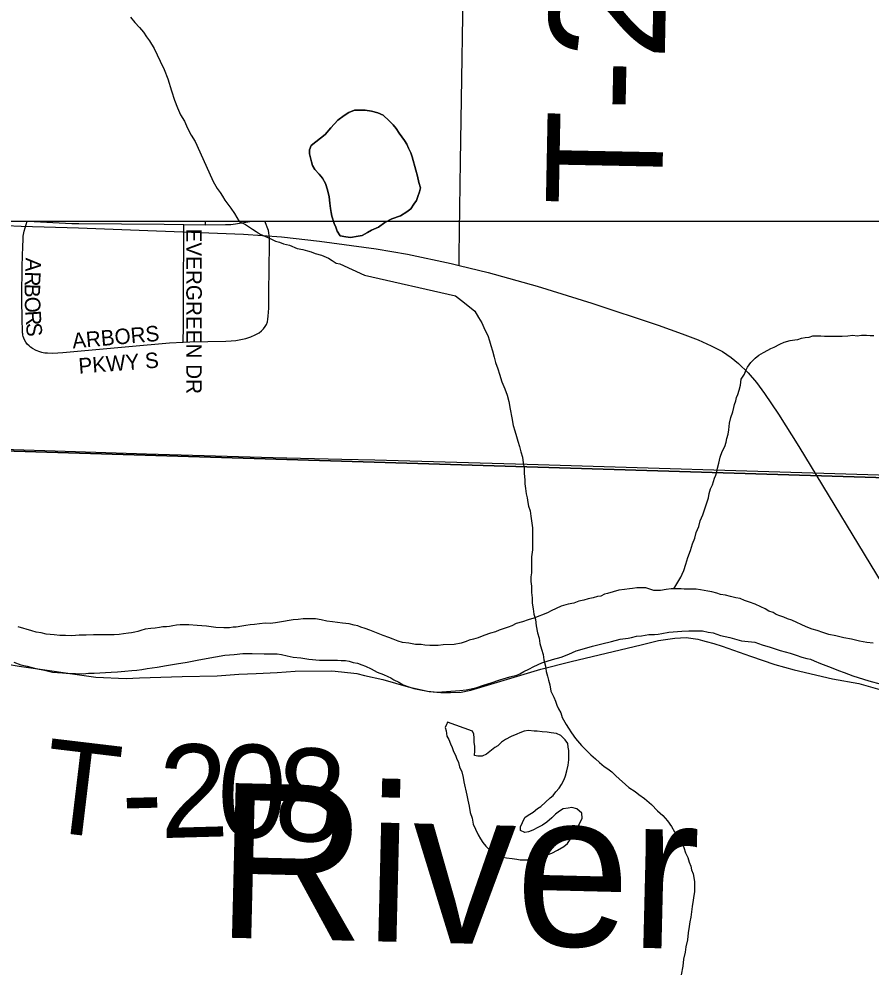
# Model space of a CAD drawing. Extents: x 0 to 68, y 0 to 52.9.
# Drawn here: x 47.168 to 47.718, y 38.053 to 38.666 of the extents above; entities that cross this region are included whole.
import ezdxf

# ---------------------------------------------------------------- set-up
doc = ezdxf.new("R2010")
doc.units = 0
for name, color, linetype in [('Default', 7, 'Continuous'), ('GM_X_Minor_Lake', 7, 'Continuous'), ('GM_X_Minor_River', 7, 'Continuous'), ('GM_X_State_Route', 7, 'Continuous'), ('GM_X_Township_Road', 7, 'Continuous'), ('GM_X_Township_Road_Text', 7, 'Continuous')]:
    doc.layers.add(name, color=color, linetype=linetype)

msp = doc.modelspace()

# ---------------------------------------------------------------- linework, layer by layer
at = {"layer": 'Default'}
msp.add_line((42.25806, 38.53508), (49.65006, 38.53508), dxfattribs=at)
for points in [[(48.1746, 38.53508), (48.17291, 38.35564), (47.10782, 38.38814), (47.10988, 38.53508)], [(47.17613, 38.45297), (47.17507, 38.45367), (47.17419, 38.45443), (47.17299, 38.45563), (47.1721, 38.4569), (47.17132, 38.45831), (47.17075, 38.45953), (47.1704, 38.46053), (47.17018, 38.46142), (47.17008, 38.4623), (47.17002, 38.463), (47.16993, 38.46404), (47.16991, 38.46579), (47.16975, 38.47014), (47.16946, 38.48614), (47.16973, 38.50602), (47.17025, 38.51888), (47.17028, 38.52313), (47.17046, 38.52544), (47.17111, 38.52868), (47.17303, 38.53508)], [(47.17327, 38.53508), (47.20189, 38.53355), (47.20636, 38.53352)], [(47.20636, 38.53352), (47.26148, 38.53314), (47.27416, 38.53294)], [(47.27374, 38.45694), (47.2739, 38.46699), (47.27393, 38.49056), (47.27418, 38.52716), (47.27416, 38.53294)], [(47.27416, 38.53294), (47.28827, 38.53272)], [(47.28827, 38.53272), (47.28829, 38.53508)], [(47.28827, 38.53272), (47.30109, 38.53287), (47.30453, 38.53298), (47.3076, 38.53335), (47.31811, 38.53508)], [(47.32574, 38.46551), (47.32682, 38.46699), (47.32759, 38.46837), (47.32825, 38.47014), (47.3286, 38.47178), (47.32878, 38.47364), (47.32905, 38.47882), (47.32917, 38.48892), (47.32961, 38.52014), (47.32955, 38.52407), (47.32943, 38.52593), (47.32912, 38.52759), (47.32887, 38.52907), (47.32666, 38.53508)], [(47.27374, 38.45694), (47.27816, 38.45718), (47.30127, 38.45753), (47.30471, 38.45773), (47.30785, 38.45806), (47.31108, 38.45858), (47.3143, 38.45932), (47.31742, 38.46034), (47.32023, 38.46163), (47.32284, 38.46303), (47.32436, 38.46424), (47.32574, 38.46551)], [(47.17613, 38.45297), (47.17863, 38.45175), (47.18085, 38.45083), (47.18214, 38.45045), (47.18427, 38.45008), (47.18614, 38.44997), (47.18943, 38.44989), (47.19601, 38.45016), (47.2387, 38.45417), (47.26498, 38.45646), (47.27374, 38.45694)], [(47.71972, 38.26238), (47.7157, 38.26283), (47.71087, 38.2637), (47.70565, 38.26497), (47.70083, 38.26584), (47.69561, 38.26712), (47.69119, 38.26798), (47.68718, 38.26923), (47.68357, 38.27049), (47.68035, 38.27133), (47.67635, 38.27299), (47.66713, 38.27713), (47.66432, 38.27797), (47.66192, 38.27921), (47.65952, 38.28005), (47.65711, 38.28088), (47.65511, 38.28211), (47.6523, 38.28295), (47.6499, 38.28459), (47.6471, 38.28583), (47.6435, 38.28749), (47.63988, 38.28874), (47.63668, 38.28999), (47.63387, 38.29123), (47.63106, 38.29167), (47.62744, 38.29252), (47.62423, 38.29337), (47.62101, 38.29381), (47.61861, 38.29464), (47.6154, 38.29549), (47.61298, 38.29592), (47.61057, 38.29636), (47.60816, 38.29679), (47.60535, 38.29723), (47.60253, 38.29727), (47.59971, 38.2973), (47.59769, 38.29733), (47.59568, 38.29736), (47.59286, 38.29739), (47.58924, 38.29744), (47.58601, 38.29708), (47.58237, 38.29633), (47.57794, 38.29639), (47.57273, 38.29806), (47.56991, 38.2981), (47.56709, 38.29813), (47.56426, 38.29777), (47.56224, 38.2974), (47.55901, 38.29704), (47.55539, 38.29668), (47.55174, 38.29552), (47.54811, 38.29437), (47.54608, 38.29399), (47.54365, 38.29282)], [(47.54365, 38.29282), (47.54164, 38.29244), (47.5388, 38.29167), (47.53557, 38.29092), (47.53274, 38.29015), (47.52951, 38.28939), (47.52627, 38.28822), (47.52264, 38.28747), (47.51819, 38.28632), (47.51495, 38.28476), (47.51171, 38.28319), (47.50927, 38.28202), (47.50037, 38.27852), (47.49673, 38.27736), (47.49309, 38.2762), (47.48904, 38.27505), (47.4862, 38.27348), (47.48378, 38.27271), (47.48054, 38.27155), (47.47811, 38.27078), (47.47568, 38.2696), (47.47245, 38.26884), (47.468, 38.26729), (47.46435, 38.26573), (47.46152, 38.26497), (47.45869, 38.2642), (47.45667, 38.26342), (47.45343, 38.26226), (47.44899, 38.26151), (47.44173, 38.26121), (47.43851, 38.26085), (47.43649, 38.26088), (47.43327, 38.26092), (47.43005, 38.26096), (47.42764, 38.26139), (47.42401, 38.26144), (47.41959, 38.2623), (47.41557, 38.26276), (47.41276, 38.2636), (47.40955, 38.26485), (47.40675, 38.26609), (47.40314, 38.26734), (47.39873, 38.26901), (47.39432, 38.27067), (47.39151, 38.27191), (47.3887, 38.27275), (47.3867, 38.27358), (47.38429, 38.27402), (47.38108, 38.27486), (47.37665, 38.27532), (47.37343, 38.27577), (47.37022, 38.27621), (47.3666, 38.27666), (47.36298, 38.27751), (47.35936, 38.27796), (47.35533, 38.27801), (47.35131, 38.27807), (47.34808, 38.27771), (47.34485, 38.27735), (47.33597, 38.27586), (47.33355, 38.27549), (47.32992, 38.27513), (47.32669, 38.27518), (47.32307, 38.27482), (47.31984, 38.27446), (47.31701, 38.2741), (47.31419, 38.27373), (47.31177, 38.27336), (47.30813, 38.27261), (47.30612, 38.27263), (47.30369, 38.27226), (47.30007, 38.27231), (47.29483, 38.27238), (47.2888, 38.27326), (47.28277, 38.27374), (47.27753, 38.27421), (47.2719, 38.27429), (47.26947, 38.27392), (47.26705, 38.27355), (47.26503, 38.27317), (47.26301, 38.2728), (47.2606, 38.27283), (47.25858, 38.27245), (47.25575, 38.27209), (47.25293, 38.27172), (47.2493, 38.27137), (47.24647, 38.2706), (47.24445, 38.26983), (47.24243, 38.26945), (47.24041, 38.26907), (47.23839, 38.2687), (47.23516, 38.26834), (47.23234, 38.26798), (47.22911, 38.26762), (47.22468, 38.26768), (47.22025, 38.26773), (47.21582, 38.26779), (47.21098, 38.26745), (47.20655, 38.26751), (47.20171, 38.26717), (47.19768, 38.26723)], [(47.19768, 38.26723), (47.19406, 38.26727), (47.19044, 38.26772), (47.18521, 38.26819), (47.18199, 38.26904), (47.17878, 38.26948), (47.17597, 38.27032), (47.16714, 38.27285)], [(47.43813, 38.23072), (47.45264, 38.23174), (47.45667, 38.23208), (47.45991, 38.23284), (47.46354, 38.2336), (47.46799, 38.23515), (47.47285, 38.23669), (47.47851, 38.23863), (47.48498, 38.24055), (47.48943, 38.2417), (47.49145, 38.24247), (47.49389, 38.24405), (47.49713, 38.24561), (47.50037, 38.24718), (47.50564, 38.24952), (47.51252, 38.25184), (47.51818, 38.25338), (47.52304, 38.25532), (47.52789, 38.25727), (47.53315, 38.2588), (47.53841, 38.26034), (47.54447, 38.26187), (47.55053, 38.2634), (47.55619, 38.26493), (47.56144, 38.26566), (47.56346, 38.26604), (47.56669, 38.2668), (47.56992, 38.26716), (47.57234, 38.26753), (47.57476, 38.2679), (47.57839, 38.26785), (47.58081, 38.26822), (47.58323, 38.26859), (47.58767, 38.26934), (47.59614, 38.27003), (47.60058, 38.27037), (47.60299, 38.27034), (47.60662, 38.27029), (47.60944, 38.27026), (47.61305, 38.2694), (47.61627, 38.26896), (47.61867, 38.26812), (47.62108, 38.26729), (47.62711, 38.26601), (47.63474, 38.2639), (47.64319, 38.26298), (47.648, 38.26131), (47.65321, 38.25964), (47.65963, 38.25754), (47.66606, 38.25585), (47.67007, 38.25459), (47.67368, 38.25334), (47.67689, 38.25249), (47.6793, 38.25206), (47.68171, 38.25082), (47.68571, 38.24916), (47.69253, 38.24666), (47.69734, 38.24459), (47.70095, 38.24334), (47.70656, 38.24126), (47.71699, 38.2379), (47.72502, 38.23579)], [(47.16443, 38.24998), (47.16884, 38.24832), (47.17286, 38.24746), (47.17607, 38.24662), (47.17969, 38.24577), (47.18411, 38.2449), (47.18933, 38.24363), (47.19577, 38.24314), (47.2006, 38.24268), (47.20422, 38.24263), (47.20905, 38.24257), (47.21268, 38.24292), (47.21631, 38.24287), (47.22719, 38.24353), (47.23123, 38.24388), (47.23607, 38.24422), (47.2405, 38.24456), (47.24373, 38.24492), (47.24696, 38.24528), (47.25059, 38.24604), (47.25704, 38.24676), (47.2631, 38.24788), (47.26956, 38.249), (47.27643, 38.25012), (47.28288, 38.25124), (47.28854, 38.25237), (47.2946, 38.2535), (47.30065, 38.25462), (47.3067, 38.25495), (47.31235, 38.25568), (47.31839, 38.2556), (47.32604, 38.2555), (47.33088, 38.25543), (47.3345, 38.25538), (47.33732, 38.25495), (47.34093, 38.25409), (47.34495, 38.25324), (47.34978, 38.25277), (47.355, 38.2519), (47.36185, 38.25141), (47.36869, 38.25132), (47.37353, 38.25126), (47.37594, 38.25122), (47.37876, 38.25119), (47.38117, 38.25075), (47.38358, 38.24992), (47.38639, 38.24948), (47.3892, 38.24824), (47.39161, 38.2474), (47.39521, 38.24575), (47.39921, 38.24369), (47.40322, 38.24203), (47.40602, 38.24078), (47.40803, 38.23996), (47.41003, 38.23872), (47.41323, 38.23707), (47.41603, 38.23543), (47.41964, 38.23418), (47.42285, 38.23293), (47.42727, 38.23207), (47.43169, 38.23121), (47.43813, 38.23072)]]:
    msp.add_lwpolyline(points, dxfattribs=at)
msp.add_lwpolyline([(47.10782, 38.38814), (48.17291, 38.35564), (48.15695, 37.30357), (47.09744, 37.33201)], close=True, dxfattribs=at)
at = {"layer": 'GM_X_Minor_Lake'}
for points in [[(47.35645, 38.58412), (47.3656, 38.59103), (47.36918, 38.5955), (47.37378, 38.60046), (47.37784, 38.60342), (47.38089, 38.60539), (47.38443, 38.60685), (47.38795, 38.60681), (47.39148, 38.60676), (47.3955, 38.60621), (47.39951, 38.60515), (47.40302, 38.6036), (47.407, 38.60003), (47.40949, 38.59749), (47.41147, 38.59495), (47.41345, 38.59191), (47.41691, 38.58734), (47.41839, 38.58481), (47.41937, 38.58229), (47.42084, 38.57926), (47.42181, 38.57673), (47.42422, 38.56816), (47.42518, 38.56413), (47.42614, 38.5601), (47.4271, 38.55657), (47.42656, 38.55407), (47.42552, 38.55107), (47.42448, 38.54857), (47.42294, 38.54608), (47.42089, 38.54309), (47.41835, 38.54112), (47.41428, 38.53866), (47.40872, 38.53672), (47.40416, 38.53427), (47.40009, 38.53131), (47.39554, 38.52936), (47.393, 38.52789), (47.38945, 38.52593), (47.38693, 38.52546), (47.38188, 38.52452), (47.37887, 38.52506), (47.37535, 38.52561), (47.37337, 38.52865), (47.3724, 38.53117), (47.37142, 38.5337), (47.36997, 38.53824), (47.3695, 38.54075), (47.36903, 38.54327), (47.36857, 38.54679), (47.36811, 38.55082), (47.36716, 38.55535), (47.3657, 38.55939), (47.36373, 38.56293), (47.36175, 38.56547), (47.35877, 38.56852), (47.35729, 38.57105), (47.35682, 38.57357), (47.35537, 38.57861), (47.3554, 38.58112), (47.35645, 38.58412)], [(47.42089, 38.54309), (47.42294, 38.54608), (47.42448, 38.54857), (47.42552, 38.55107), (47.42656, 38.55407), (47.4271, 38.55657), (47.42614, 38.5601), (47.42518, 38.56413), (47.42422, 38.56816), (47.42181, 38.57673), (47.42084, 38.57926), (47.41937, 38.58229), (47.41839, 38.58481), (47.41691, 38.58734), (47.41345, 38.59191), (47.41147, 38.59495), (47.40949, 38.59749), (47.407, 38.60003), (47.40302, 38.6036), (47.39951, 38.60515), (47.3955, 38.60621), (47.39148, 38.60676), (47.38795, 38.60681), (47.38443, 38.60685), (47.38089, 38.60539), (47.37784, 38.60342), (47.37378, 38.60046), (47.36918, 38.5955), (47.3656, 38.59103), (47.35645, 38.58412)], [(47.35645, 38.58412), (47.3554, 38.58112), (47.35537, 38.57861), (47.35682, 38.57357), (47.35729, 38.57105), (47.35877, 38.56852), (47.36175, 38.56547), (47.36373, 38.56293), (47.3657, 38.55939), (47.36716, 38.55535), (47.36811, 38.55082), (47.36857, 38.54679), (47.36903, 38.54327), (47.3695, 38.54075), (47.36997, 38.53824), (47.37142, 38.5337), (47.3724, 38.53117), (47.37337, 38.52865), (47.37535, 38.52561), (47.37887, 38.52506), (47.38188, 38.52452), (47.38693, 38.52546), (47.38945, 38.52593), (47.393, 38.52789), (47.39554, 38.52936), (47.40009, 38.53131), (47.40416, 38.53427), (47.40872, 38.53672), (47.41428, 38.53866), (47.41835, 38.54112), (47.42089, 38.54309)], [(47.44473, 38.21135), (47.44432, 38.21055), (47.4439, 38.20975), (47.44307, 38.20775), (47.44385, 38.20573), (47.44421, 38.20211), (47.44539, 38.20009), (47.44656, 38.19726), (47.44774, 38.19483), (47.44852, 38.19241), (47.4497, 38.18999), (47.45048, 38.18797), (47.45165, 38.18514), (47.45242, 38.18232), (47.45399, 38.17908), (47.45475, 38.17546), (47.45512, 38.17264)], [(47.45512, 38.17264), (47.45702, 38.16418), (47.45779, 38.16095), (47.45854, 38.15692), (47.4593, 38.1529), (47.46046, 38.14926), (47.46122, 38.14523), (47.46279, 38.142), (47.46435, 38.13836), (47.46593, 38.13593), (47.46751, 38.1335), (47.4695, 38.13106), (47.47149, 38.12903), (47.47348, 38.12739), (47.47707, 38.12494), (47.48029, 38.12409), (47.4827, 38.12366), (47.48632, 38.12321), (47.48954, 38.12277), (47.49154, 38.12234), (47.49356, 38.12231), (47.49678, 38.12227), (47.4988, 38.12264), (47.50082, 38.12302), (47.50325, 38.12379), (47.50526, 38.12416), (47.50729, 38.12494), (47.51214, 38.12648), (47.51579, 38.12845), (47.51985, 38.1308), (47.52229, 38.13278), (47.52353, 38.13477), (47.52476, 38.13677), (47.52641, 38.13956), (47.52888, 38.14354), (47.53053, 38.14674), (47.53177, 38.14913), (47.5314, 38.15235), (47.52822, 38.1552), (47.525, 38.15605), (47.52258, 38.15568), (47.51936, 38.15532), (47.51692, 38.15374), (47.51448, 38.15177), (47.51203, 38.14939), (47.50877, 38.14662), (47.50593, 38.14465), (47.50309, 38.14308), (47.49984, 38.14151), (47.49701, 38.14035), (47.49459, 38.13997), (47.49178, 38.14122), (47.49181, 38.14363), (47.49306, 38.14643), (47.49471, 38.14962), (47.49674, 38.1512), (47.49999, 38.15316), (47.50284, 38.15554), (47.50487, 38.15672), (47.51098, 38.16226), (47.51302, 38.16384), (47.51466, 38.16623), (47.5167, 38.16862), (47.51834, 38.171), (47.52, 38.1742), (47.52083, 38.1766), (47.52168, 38.1798), (47.52253, 38.1834), (47.52298, 38.18701), (47.52302, 38.19023), (47.52305, 38.19304), (47.52268, 38.19506), (47.5223, 38.19747), (47.52072, 38.1999), (47.51794, 38.20275), (47.51514, 38.20399), (47.51152, 38.20444), (47.5091, 38.20488), (47.50588, 38.20492), (47.50266, 38.20536), (47.50065, 38.20539), (47.49703, 38.20584), (47.49421, 38.20547), (47.49137, 38.20431), (47.48935, 38.20353), (47.4857, 38.20197), (47.48205, 38.20001), (47.47961, 38.19843), (47.47717, 38.19605), (47.47514, 38.19487), (47.46985, 38.19052), (47.46701, 38.18936), (47.46419, 38.18939), (47.46218, 38.18982), (47.46222, 38.19263), (47.46225, 38.19545), (47.46189, 38.19826), (47.46192, 38.20108), (47.46155, 38.20349), (47.46077, 38.20551), (47.44473, 38.21135)]]:
    msp.add_lwpolyline(points, dxfattribs=at)
at = {"layer": 'GM_X_Minor_River'}
for points in [[(47.23966, 38.66701), (47.24264, 38.66346), (47.24562, 38.66041), (47.2481, 38.65736), (47.25008, 38.65432), (47.25206, 38.65178), (47.25502, 38.64672), (47.25698, 38.64268), (47.25894, 38.63864), (47.26139, 38.63308), (47.26383, 38.62702), (47.26626, 38.61945), (47.26819, 38.6134), (47.27014, 38.60835), (47.2721, 38.60381), (47.27457, 38.59976), (47.27652, 38.59521), (47.27898, 38.59066), (47.28145, 38.58661), (47.29027, 38.56691), (47.29321, 38.56084), (47.29567, 38.55629), (47.29765, 38.55375), (47.29913, 38.55122), (47.30061, 38.54869), (47.3026, 38.54615), (47.30458, 38.54361), (47.30705, 38.54007), (47.31001, 38.535), (47.31401, 38.53294), (47.3185, 38.52987), (47.321, 38.52833), (47.3235, 38.52679), (47.327, 38.52524), (47.33051, 38.52368), (47.33351, 38.52214), (47.33602, 38.5216), (47.33853, 38.52057), (47.34254, 38.51951), (47.34755, 38.51743), (47.35107, 38.51689), (47.35408, 38.51584), (47.35659, 38.51531), (47.35909, 38.51427), (47.36311, 38.51321), (47.36761, 38.51115), (47.37011, 38.50961), (47.37261, 38.50807), (47.37512, 38.50753), (47.39094, 38.50017)], [(47.39094, 38.50017), (47.44971, 38.48694), (47.45372, 38.48392), (47.45672, 38.4814), (47.46223, 38.47687), (47.46473, 38.47285), (47.46673, 38.46933), (47.46872, 38.46481), (47.47072, 38.46129), (47.47172, 38.45778), (47.47271, 38.45476), (47.47371, 38.45125), (47.4747, 38.44723), (47.4757, 38.44372), (47.4772, 38.4397), (47.47819, 38.43619), (47.47968, 38.43116), (47.48168, 38.42664), (47.48318, 38.42262), (47.48417, 38.41861), (47.48516, 38.41359), (47.48615, 38.40807), (47.48714, 38.40305), (47.48814, 38.39953), (47.48914, 38.39602), (47.49013, 38.393), (47.49113, 38.38949), (47.49212, 38.38597), (47.49312, 38.38246), (47.49361, 38.37895), (47.49411, 38.37543), (47.4941, 38.37192), (47.49459, 38.36791), (47.49458, 38.3654), (47.49508, 38.36239), (47.49557, 38.35887), (47.49607, 38.35637), (47.49656, 38.35335), (47.49706, 38.35084), (47.49806, 38.34783), (47.49855, 38.34432), (47.49904, 38.3398), (47.49954, 38.33679), (47.49952, 38.32826), (47.49951, 38.32575), (47.4995, 38.32274), (47.49899, 38.31823), (47.49898, 38.31472), (47.49897, 38.3102), (47.49897, 38.30769), (47.49846, 38.30519), (47.49845, 38.30218), (47.49895, 38.29917), (47.49894, 38.29515), (47.49943, 38.29164), (47.49942, 38.28813), (47.49992, 38.28461), (47.50041, 38.2811), (47.50141, 38.27759), (47.5019, 38.27357), (47.50289, 38.26905), (47.50389, 38.26554), (47.50438, 38.26203), (47.50538, 38.25851), (47.50637, 38.255), (47.50686, 38.25148), (47.50786, 38.24747), (47.50835, 38.24395), (47.50935, 38.24094), (47.50984, 38.23843), (47.51084, 38.23542), (47.51133, 38.2314), (47.51333, 38.22738), (47.51433, 38.22487), (47.51533, 38.22236), (47.51632, 38.21985), (47.51782, 38.21734), (47.51882, 38.21432), (47.52132, 38.2098), (47.52282, 38.20729), (47.52482, 38.20427), (47.52732, 38.20075), (47.53132, 38.19622), (47.53433, 38.1932), (47.53733, 38.19018), (47.54033, 38.18767), (47.54283, 38.18515), (47.54584, 38.18263), (47.54834, 38.18112), (47.55085, 38.1791), (47.55335, 38.17659), (47.56186, 38.16904), (47.56587, 38.16651), (47.56837, 38.1645), (47.57188, 38.16198), (47.57639, 38.15795), (47.58039, 38.15393), (47.5839, 38.15091), (47.5869, 38.14739), (47.5894, 38.14386), (47.5914, 38.14035)], [(47.59092, 38.29742), (47.59537, 38.30499), (47.5962, 38.30699), (47.59744, 38.30939), (47.5987, 38.31339), (47.59997, 38.31779), (47.60163, 38.32219), (47.6029, 38.32659), (47.60455, 38.33019), (47.60541, 38.33379), (47.60707, 38.33779), (47.60792, 38.34139), (47.60958, 38.34539), (47.61251, 38.35379), (47.61334, 38.35619), (47.61378, 38.359), (47.61463, 38.3622), (47.61587, 38.36459), (47.61713, 38.369), (47.61796, 38.371), (47.61879, 38.37299), (47.61923, 38.3754), (47.62007, 38.3786), (47.62093, 38.38261), (47.62218, 38.38621), (47.62384, 38.3894), (47.62468, 38.3922), (47.62511, 38.39461), (47.62595, 38.39741), (47.62639, 38.40022), (47.62685, 38.40463), (47.6277, 38.40823), (47.62895, 38.41183), (47.62979, 38.41464), (47.63022, 38.41664), (47.63106, 38.41904), (47.63149, 38.42104), (47.63232, 38.42304), (47.63316, 38.42584), (47.63401, 38.42904), (47.63446, 38.43306), (47.63651, 38.43624), (47.63735, 38.43864), (47.63858, 38.44064), (47.64064, 38.44382), (47.64349, 38.4466), (47.64594, 38.44857), (47.64878, 38.45014), (47.65162, 38.45171), (47.65365, 38.45289), (47.65567, 38.45367), (47.65932, 38.45563), (47.66216, 38.4568), (47.6662, 38.45795), (47.66902, 38.45832), (47.67104, 38.45869), (47.67347, 38.45946), (47.67589, 38.45983), (47.67831, 38.4602), (47.68074, 38.46097), (47.68316, 38.46094), (47.68598, 38.46091), (47.68839, 38.46087), (47.69081, 38.46084), (47.69282, 38.46082), (47.69645, 38.46077), (47.69967, 38.46073), (47.7033, 38.46108), (47.70653, 38.46144), (47.70934, 38.461), (47.71217, 38.46137), (47.71539, 38.46132), (47.71781, 38.46129), (47.72022, 38.46126)], [(47.5914, 38.14035), (47.5934, 38.13783), (47.5954, 38.13431), (47.5974, 38.13029), (47.59839, 38.12678), (47.59989, 38.12377), (47.60088, 38.12075), (47.60188, 38.11824), (47.60238, 38.11573), (47.60338, 38.11322), (47.60437, 38.1082), (47.60436, 38.10519), (47.60435, 38.10168), (47.60385, 38.09917), (47.60334, 38.09616), (47.60283, 38.09215), (47.60232, 38.08864), (47.60181, 38.08513), (47.6013, 38.08212), (47.60079, 38.07912), (47.60028, 38.0751), (47.59977, 38.07059), (47.59875, 38.06608), (47.59824, 38.06257), (47.59723, 38.05806), (47.59672, 38.05354), (47.5957, 38.04803)]]:
    msp.add_lwpolyline(points, dxfattribs=at)
at = {"layer": 'GM_X_State_Route'}
for points in [[(46.80943, 38.66708), (46.82386, 38.65937), (46.8826, 38.63006), (46.98861, 38.57593), (47.01807, 38.56147), (47.03299, 38.55475), (47.04821, 38.54875), (47.05983, 38.54493), (47.0756, 38.54067), (47.09163, 38.53749), (47.10374, 38.53567), (47.12035, 38.53414), (47.16917, 38.53186), (47.20611, 38.53072), (47.31276, 38.52664), (47.33737, 38.52491), (47.36189, 38.5222), (47.39852, 38.51713), (47.4188, 38.51373), (47.44696, 38.50778), (47.4521, 38.50651)], [(47.4521, 38.50651), (47.47091, 38.50189), (47.5026, 38.49314), (47.53791, 38.48219), (47.58079, 38.46787), (47.5963, 38.46225), (47.6066, 38.45833), (47.61496, 38.45457), (47.62228, 38.45081), (47.62792, 38.44705), (47.63273, 38.44308), (47.63901, 38.43702), (47.64424, 38.43075), (47.64947, 38.42365), (47.6586, 38.4104), (47.67171, 38.38946), (47.72913, 38.29467)], [(46.89942, 38.39698), (46.94005, 38.3952), (47.01248, 38.39244), (47.04831, 38.39119), (47.0711, 38.3904), (47.09079, 38.38961), (47.1101, 38.3893), (47.19098, 38.38658), (47.25002, 38.3847), (47.33202, 38.38237), (47.37632, 38.38135), (47.39764, 38.38085), (47.49605, 38.37804), (47.70927, 38.37158), (47.80767, 38.36846), (47.90586, 38.36525), (47.91535, 38.36494)]]:
    msp.add_lwpolyline(points, dxfattribs=at)
at = {"layer": 'GM_X_Township_Road'}
for points in [[(47.4521, 38.50651), (47.45219, 38.51339), (47.45292, 38.57364), (47.45541, 38.72138), (47.45703, 38.81578), (47.45916, 38.92248), (47.46317, 39.13998), (47.46368, 39.18925), (47.46464, 39.23847), (47.46647, 39.36981), (47.46724, 39.39853), (47.46711, 39.41167)], [(47.14497, 38.25139), (47.16785, 38.24738), (47.21725, 38.24034), (47.23697, 38.23947), (47.24564, 38.23992), (47.27308, 38.24071), (47.29569, 38.2413), (47.30979, 38.24226), (47.32099, 38.24266), (47.33452, 38.24344), (47.34611, 38.24421), (47.36983, 38.24449), (47.37615, 38.2437), (47.38592, 38.24268), (47.39094, 38.24153), (47.40292, 38.23883), (47.41915, 38.2342), (47.43268, 38.23111), (47.44041, 38.23034), (47.44659, 38.23035), (47.45355, 38.23073), (47.45973, 38.2319), (47.46823, 38.23461), (47.50494, 38.24544), (47.52464, 38.25047), (47.56985, 38.26131), (47.58105, 38.26402), (47.59151, 38.26562), (47.59883, 38.26596), (47.60641, 38.26486), (47.60937, 38.26414), (47.61186, 38.26333), (47.61668, 38.26204), (47.62207, 38.26041), (47.64049, 38.25388), (47.65611, 38.24855), (47.66863, 38.24503), (47.69355, 38.23917), (47.71052, 38.23625), (47.73304, 38.22971)]]:
    msp.add_lwpolyline(points, dxfattribs=at)

# ---------------------------------------------------------------- texts
at = {"layer": 'Default'}
for s, height, rotation, p in [('EVERGREEN DR', 0.01, 270, (47.27581, 38.53036)), ('A', 0.01, 268.07628, (47.17197, 38.51155)), ('R', 0.01, 268.10437, (47.17168, 38.50275)), ('B', 0.01, 268.81821, (47.17141, 38.4947)), ('O', 0.01, 272.8121, (47.17125, 38.48602)), ('R', 0.01, 273.80557, (47.1717, 38.47704)), ('S', 0.01, 273.84305, (47.17222, 38.46913)), ('ARBORS', 0.01, 5.10327, (47.20248, 38.45277)), ('PKWY S', 0.01, 4.40096, (47.20649, 38.4365)), ('River', 0.100042, 358.59636, (47.29433, 38.07214))]:
    msp.add_text(s, height=height, rotation=rotation, dxfattribs=at).set_placement(p)
at = {"layer": 'GM_X_Township_Road_Text'}
for s, height, rotation, p in [('T-234', 0.075, 88.87238, (47.58316, 38.54438)), ('T', 0.06, 353.19552, (47.18037, 38.14138)), ('2', 0.06, 1.58784, (47.25913, 38.13628)), ('0', 0.06, 358.29283, (47.29516, 38.13731)), ('8', 0.06, 355.05528, (47.33121, 38.13626)), ('-', 0.06, 1.53964, (47.23444, 38.13562))]:
    msp.add_text(s, height=height, rotation=rotation, dxfattribs=at).set_placement(p)

doc.saveas('drawing.dxf')
